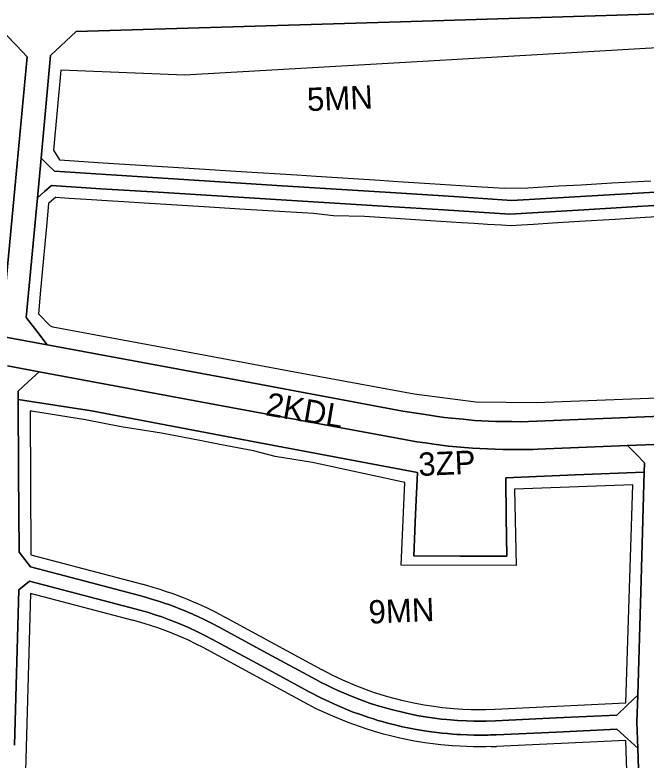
# Model space of a CAD drawing. Extents: x 7418021 to 7419743, y 5540231 to 5541685.
# Drawn here: x 7419069.1 to 7419339.9, y 5540706.1 to 5541025.9 of the extents above; entities that cross this region are included whole.
import ezdxf

# ---------------------------------------------------------------- set-up
doc = ezdxf.new("R2010")
doc.units = 0
for name, color, linetype in [('linie_rozgraniczajace', 7, 'Continuous'), ('linie_zabudowy_nieprzekraczalne', 7, 'Continuous'), ('linie_zabudowy_obowiazujace', 7, 'Continuous'), ('oznaczenia_przeznaczen', 7, 'Continuous')]:
    doc.layers.add(name, color=color, linetype=linetype)

msp = doc.modelspace()

# ---------------------------------------------------------------- linework, layer by layer
at = {"layer": 'linie_rozgraniczajace'}
for points in [[(7419373.79, 5541027.27), (7419234.54, 5541023), (7419095.29, 5541018.74), (7419084.37, 5541008.48), (7419080.29, 5540964.41), (7419078.72, 5540947.43), (7419073.96, 5540896.09), (7419078.43, 5540890.2), (7419082.87, 5540884.31), (7419053.34, 5540889.78), (7419058.73, 5540893.85), (7419064.09, 5540897.92), (7419069.18, 5540952.92), (7419074.28, 5541007.93), (7419069.74, 5541012.72), (7419065.21, 5541017.52), (7419045.63, 5541016.89), (7419026.05, 5541016.25), (7419014.29, 5541017.62), (7419002.54, 5541018.98), (7418996.01, 5541020.4), (7418989.47, 5541021.83), (7418984.55, 5541023.35), (7418974.12, 5541026.58)], [(7419065.21, 5541017.52), (7419069.74, 5541012.72), (7419074.28, 5541007.93), (7419069.18, 5540952.92), (7419064.09, 5540897.92)], [(7419363.96, 5540945.38), (7419313.1, 5540942.32), (7419281.37, 5540940.41), (7419252.97, 5540942.22), (7419224.57, 5540944.04), (7419130.54, 5540949.78), (7419105.96, 5540951.31), (7419084.74, 5540952.69), (7419081.73, 5540950.06), (7419078.72, 5540947.43), (7419080.29, 5540964.41), (7419083.17, 5540961.6), (7419086.04, 5540958.8), (7419134.88, 5540955.7), (7419183.71, 5540952.61), (7419232.55, 5540949.52), (7419257.39, 5540947.92), (7419282.22, 5540946.32), (7419385.59, 5540952.23)], [(7419470.75, 5540858.74), (7419292.97, 5540851.53), (7419285.88, 5540851.34), (7419282.27, 5540851.35), (7419278.66, 5540851.37), (7419275.44, 5540851.47), (7419272.23, 5540851.57), (7419269.25, 5540851.74), (7419266.27, 5540851.91), (7419261.35, 5540852.36), (7419256.44, 5540852.8), (7419253.43, 5540853.17), (7419250.42, 5540853.54), (7419246.95, 5540854.07), (7419241.21, 5540854.99), (7419235.47, 5540855.91), (7419160.91, 5540869.85), (7419082.87, 5540884.31), (7419078.43, 5540890.2), (7419073.96, 5540896.09), (7419078.72, 5540947.43), (7419081.73, 5540950.06), (7419084.74, 5540952.69), (7419105.96, 5540951.31), (7419130.54, 5540949.78), (7419224.57, 5540944.04), (7419252.97, 5540942.22), (7419281.37, 5540940.41), (7419313.1, 5540942.32), (7419363.96, 5540945.38)], [(7419053.34, 5540889.78), (7419082.87, 5540884.31), (7419160.91, 5540869.85), (7419235.47, 5540855.91), (7419241.21, 5540854.99), (7419246.95, 5540854.07), (7419250.42, 5540853.54), (7419253.43, 5540853.17), (7419256.44, 5540852.8), (7419261.35, 5540852.36), (7419266.27, 5540851.91), (7419269.25, 5540851.74), (7419272.23, 5540851.57), (7419275.44, 5540851.47), (7419278.66, 5540851.37), (7419282.27, 5540851.35), (7419285.88, 5540851.34), (7419292.97, 5540851.53), (7419470.75, 5540858.74)], [(7419355.09, 5540842.04), (7419331.92, 5540841.1), (7419293.45, 5540839.54), (7419291.47, 5540839.47), (7419289.57, 5540839.41), (7419287.68, 5540839.37), (7419285.97, 5540839.34), (7419282.21, 5540839.36), (7419278.45, 5540839.37), (7419275.07, 5540839.48), (7419268.54, 5540839.76), (7419265.39, 5540839.94), (7419260.27, 5540840.41), (7419255.16, 5540840.87), (7419251.98, 5540841.26), (7419248.79, 5540841.65), (7419245.17, 5540842.2), (7419241.54, 5540842.75), (7419236.87, 5540843.57), (7419158.72, 5540858.05), (7419079.41, 5540872.75), (7419065.92, 5540875.25)], [(7419065.92, 5540875.25), (7419079.41, 5540872.75), (7419074.91, 5540868.61), (7419070.4, 5540864.47), (7419070.43, 5540860.86), (7419070.67, 5540829.88), (7419070.94, 5540795.28), (7419073.38, 5540792.15), (7419075.81, 5540789.01), (7419099.2, 5540782.86), (7419122.58, 5540776.71), (7419124.13, 5540776.29), (7419125.48, 5540775.9), (7419126.83, 5540775.52), (7419128.28, 5540775.08), (7419131.08, 5540774.2), (7419132.43, 5540773.76), (7419133.56, 5540773.37), (7419134.68, 5540772.98), (7419136.93, 5540772.17), (7419138.18, 5540771.69), (7419139.44, 5540771.21), (7419140.47, 5540770.79), (7419142.4, 5540770.01), (7419144.23, 5540769.23), (7419145.17, 5540768.83), (7419146.18, 5540768.37), (7419147.2, 5540767.92), (7419148.17, 5540767.47), (7419149.94, 5540766.63), (7419151.73, 5540765.75), (7419153.73, 5540764.74), (7419156.66, 5540763.2), (7419177.42, 5540751.92), (7419198.19, 5540740.64), (7419200.51, 5540739.43), (7419202.84, 5540738.23), (7419205.21, 5540737.1), (7419207.59, 5540735.97), (7419210.3, 5540734.8), (7419213.02, 5540733.63), (7419217.1, 5540732.11), (7419221.18, 5540730.6), (7419224.34, 5540729.6), (7419227.5, 5540728.61), (7419230.6, 5540727.79), (7419236.48, 5540726.35), (7419241.53, 5540725.31), (7419245.94, 5540724.56), (7419248.08, 5540724.23), (7419250.04, 5540723.98), (7419251.99, 5540723.74), (7419254.45, 5540723.5), (7419258.95, 5540723.14), (7419262.85, 5540722.94), (7419266.01, 5540722.85), (7419271.2, 5540722.85), (7419275.25, 5540722.99), (7419301.31, 5540724.21), (7419327.38, 5540725.44), (7419331.82, 5540729.73), (7419336.27, 5540734.01), (7419335.88, 5540722.36), (7419336.33, 5540711.28), (7419331.84, 5540715.3), (7419327.34, 5540719.32), (7419301.44, 5540718.16), (7419275.53, 5540716.99), (7419274.33, 5540716.95), (7419273.13, 5540716.9), (7419272.07, 5540716.87), (7419271, 5540716.85), (7419268.45, 5540716.85), (7419265.91, 5540716.84), (7419263.1, 5540716.94), (7419260.29, 5540717.04), (7419258.64, 5540717.14), (7419256.99, 5540717.25), (7419254.65, 5540717.46), (7419252.31, 5540717.67), (7419249, 5540718.09), (7419245.7, 5540718.51), (7419241.43, 5540719.21), (7419238.36, 5540719.82), (7419235.3, 5540720.44), (7419233.66, 5540720.82), (7419232.03, 5540721.19), (7419230.26, 5540721.65), (7419228.49, 5540722.1), (7419226.63, 5540722.63), (7419224.76, 5540723.16), (7419222.87, 5540723.75), (7419220.98, 5540724.34), (7419217.38, 5540725.61), (7419213.78, 5540726.89), (7419207.4, 5540729.48), (7419200.58, 5540732.65), (7419195.33, 5540735.37), (7419174.56, 5540746.65)], [(7419331.92, 5540841.1), (7419355.09, 5540842.04)], [(7419337.76, 5540666.96), (7419336.33, 5540711.28), (7419335.88, 5540722.36), (7419336.27, 5540734.01), (7419337.57, 5540778.37), (7419339.07, 5540829.66), (7419339.19, 5540833.66), (7419335.55, 5540837.38), (7419331.92, 5540841.1)], [(7419174.56, 5540746.65), (7419153.8, 5540757.92), (7419150.61, 5540759.6), (7419147.34, 5540761.21), (7419143.54, 5540762.98), (7419141.77, 5540763.76), (7419139.85, 5540764.56), (7419137.94, 5540765.35), (7419135, 5540766.44), (7419132.07, 5540767.54), (7419129.22, 5540768.47), (7419126.36, 5540769.4), (7419121.05, 5540770.9), (7419098.18, 5540776.92), (7419075.31, 5540782.94), (7419073.03, 5540781.08), (7419070.75, 5540779.22), (7419068.86, 5540712.48)], [(7419068.86, 5540712.48), (7419070.75, 5540779.22), (7419073.03, 5540781.08), (7419075.31, 5540782.94), (7419098.18, 5540776.92), (7419121.05, 5540770.9), (7419126.36, 5540769.4), (7419129.22, 5540768.47), (7419132.07, 5540767.54), (7419135, 5540766.44), (7419137.94, 5540765.35), (7419139.85, 5540764.56), (7419141.77, 5540763.76), (7419143.54, 5540762.98), (7419147.34, 5540761.21), (7419150.61, 5540759.6), (7419153.8, 5540757.92), (7419174.56, 5540746.65), (7419195.33, 5540735.37), (7419200.58, 5540732.65), (7419207.4, 5540729.48), (7419213.78, 5540726.89), (7419217.38, 5540725.61), (7419220.98, 5540724.34), (7419222.87, 5540723.75), (7419224.76, 5540723.16), (7419226.63, 5540722.63), (7419228.49, 5540722.1), (7419230.26, 5540721.65), (7419232.03, 5540721.19), (7419233.66, 5540720.82), (7419235.3, 5540720.44), (7419238.36, 5540719.82), (7419241.43, 5540719.21), (7419245.7, 5540718.51), (7419249, 5540718.09), (7419252.31, 5540717.67), (7419254.65, 5540717.46), (7419256.99, 5540717.25), (7419258.64, 5540717.14), (7419260.29, 5540717.04), (7419263.1, 5540716.94), (7419265.91, 5540716.84), (7419268.45, 5540716.85), (7419271, 5540716.85), (7419272.07, 5540716.87), (7419273.13, 5540716.9), (7419274.33, 5540716.95), (7419275.53, 5540716.99), (7419301.44, 5540718.16), (7419327.34, 5540719.32), (7419331.84, 5540715.3), (7419336.33, 5540711.28), (7419337.76, 5540666.96)]]:
    msp.add_lwpolyline(points, dxfattribs=at)
for points in [[(7419095.29, 5541018.74), (7419234.54, 5541023), (7419373.79, 5541027.27), (7419464.79, 5541028.03), (7419557.71, 5541028.81), (7419559.74, 5541026.38), (7419561.78, 5541023.94), (7419553.94, 5540993.88), (7419546.61, 5540965.74), (7419543.38, 5540963.37), (7419540.14, 5540961), (7419488.96, 5540958.13), (7419385.59, 5540952.23), (7419282.22, 5540946.32), (7419257.39, 5540947.92), (7419232.55, 5540949.52), (7419183.71, 5540952.61), (7419134.88, 5540955.7), (7419086.04, 5540958.8), (7419083.17, 5540961.6), (7419080.29, 5540964.41), (7419084.37, 5541008.48)], [(7419079.41, 5540872.75), (7419158.72, 5540858.05), (7419236.87, 5540843.57), (7419241.54, 5540842.75), (7419245.17, 5540842.2), (7419248.79, 5540841.65), (7419251.98, 5540841.26), (7419255.16, 5540840.87), (7419260.27, 5540840.41), (7419265.39, 5540839.94), (7419268.54, 5540839.76), (7419275.07, 5540839.48), (7419278.45, 5540839.37), (7419282.21, 5540839.36), (7419285.97, 5540839.34), (7419287.68, 5540839.37), (7419289.57, 5540839.41), (7419291.47, 5540839.47), (7419293.45, 5540839.54), (7419331.92, 5540841.1), (7419335.55, 5540837.38), (7419339.19, 5540833.66), (7419339.07, 5540829.66), (7419309.4, 5540828.46), (7419279.74, 5540827.25), (7419279.9, 5540810.41), (7419280.06, 5540793.57), (7419260.12, 5540793.66), (7419240.17, 5540793.74), (7419241, 5540811.6), (7419241.82, 5540829.46), (7419171.88, 5540842.73), (7419101.94, 5540856.01), (7419086.18, 5540858.43), (7419070.43, 5540860.86), (7419070.4, 5540864.47), (7419074.91, 5540868.61)], [(7419070.43, 5540860.86), (7419086.18, 5540858.43), (7419101.94, 5540856.01), (7419171.88, 5540842.73), (7419241.82, 5540829.46), (7419241, 5540811.6), (7419240.17, 5540793.74), (7419260.12, 5540793.66), (7419280.06, 5540793.57), (7419279.9, 5540810.41), (7419279.74, 5540827.25), (7419309.4, 5540828.46), (7419339.07, 5540829.66), (7419337.57, 5540778.37), (7419336.27, 5540734.01), (7419331.82, 5540729.73), (7419327.38, 5540725.44), (7419301.31, 5540724.21), (7419275.25, 5540722.99), (7419271.2, 5540722.85), (7419266.01, 5540722.85), (7419262.85, 5540722.94), (7419258.95, 5540723.14), (7419254.45, 5540723.5), (7419251.99, 5540723.74), (7419250.04, 5540723.98), (7419248.08, 5540724.23), (7419245.94, 5540724.56), (7419241.53, 5540725.31), (7419236.48, 5540726.35), (7419230.6, 5540727.79), (7419227.5, 5540728.61), (7419224.34, 5540729.6), (7419221.18, 5540730.6), (7419217.1, 5540732.11), (7419213.02, 5540733.63), (7419210.3, 5540734.8), (7419207.59, 5540735.97), (7419205.21, 5540737.1), (7419202.84, 5540738.23), (7419200.51, 5540739.43), (7419198.19, 5540740.64), (7419177.42, 5540751.92), (7419156.66, 5540763.2), (7419153.73, 5540764.74), (7419151.73, 5540765.75), (7419149.94, 5540766.63), (7419148.17, 5540767.47), (7419147.2, 5540767.92), (7419146.18, 5540768.37), (7419145.17, 5540768.83), (7419144.23, 5540769.23), (7419142.4, 5540770.01), (7419140.47, 5540770.79), (7419139.44, 5540771.21), (7419138.18, 5540771.69), (7419136.93, 5540772.17), (7419134.68, 5540772.98), (7419133.56, 5540773.37), (7419132.43, 5540773.76), (7419131.08, 5540774.2), (7419128.28, 5540775.08), (7419126.83, 5540775.52), (7419125.48, 5540775.9), (7419124.13, 5540776.29), (7419122.58, 5540776.71), (7419099.2, 5540782.86), (7419075.81, 5540789.01), (7419073.38, 5540792.15), (7419070.94, 5540795.28), (7419070.67, 5540829.88)]]:
    msp.add_lwpolyline(points, close=True, dxfattribs=at)
at = {"layer": 'linie_zabudowy_nieprzekraczalne'}
for points in [[(7419383.77, 5541014.03), (7419244.03, 5541005.91)], [(7419244.03, 5541005.91), (7419142.02, 5540999.99)], [(7419088.81, 5541002.19), (7419085.63, 5540967.79)], [(7419142.02, 5540999.99), (7419088.81, 5541002.19)], [(7419085.63, 5540967.79), (7419088.2, 5540963.67)], [(7419088.2, 5540963.67), (7419106.97, 5540962.48)], [(7419106.97, 5540962.48), (7419141.6, 5540960.29)], [(7419141.6, 5540960.29), (7419166.21, 5540958.73)], [(7419166.21, 5540958.73), (7419189.96, 5540957.23)], [(7419189.96, 5540957.23), (7419198.32, 5540956.7)], [(7419198.32, 5540956.7), (7419225.69, 5540954.96)], [(7419225.69, 5540954.96), (7419233.35, 5540954.48)], [(7419233.35, 5540954.48), (7419247.13, 5540953.59)], [(7419247.13, 5540953.59), (7419264.82, 5540952.45)], [(7419264.82, 5540952.45), (7419279.05, 5540951.54)], [(7419289.19, 5540951.73), (7419302.45, 5540952.49)], [(7419302.45, 5540952.49), (7419312, 5540953.03)], [(7419312, 5540953.03), (7419325.1, 5540953.78)], [(7419325.1, 5540953.78), (7419341.84, 5540954.74)], [(7419279.05, 5540951.54), (7419289.19, 5540951.73)], [(7419086.57, 5540947.65), (7419083.51, 5540944.98)], [(7419086.48, 5540947.57), (7419083.51, 5540944.98)], [(7419092.37, 5540947.19), (7419086.48, 5540947.57)], [(7419099.58, 5540946.72), (7419092.37, 5540947.19)], [(7419110.89, 5540946), (7419099.58, 5540946.72)], [(7419083.51, 5540944.98), (7419082.6, 5540935.07)], [(7419115.87, 5540945.69), (7419110.89, 5540946)], [(7419124.48, 5540945.15), (7419115.87, 5540945.69)], [(7419138.53, 5540944.27), (7419124.48, 5540945.15)], [(7419154.64, 5540943.27), (7419138.53, 5540944.27)], [(7419165.5, 5540942.61), (7419154.64, 5540943.27)], [(7419411.21, 5540943.03), (7419339.5, 5540938.9)], [(7419197.15, 5540940.69), (7419165.5, 5540942.61)], [(7419205.76, 5540939.69), (7419197.15, 5540940.69)], [(7419219.03, 5540939.37), (7419205.76, 5540939.69)], [(7419234.47, 5540938.4), (7419219.03, 5540939.37)], [(7419247.41, 5540937.57), (7419234.47, 5540938.4)], [(7419260.66, 5540936.73), (7419247.41, 5540937.57)], [(7419266.1, 5540936.38), (7419260.66, 5540936.73)], [(7419299.77, 5540936.51), (7419291.62, 5540936.02)], [(7419311.27, 5540937.2), (7419299.77, 5540936.51)], [(7419326.57, 5540938.13), (7419311.27, 5540937.2)], [(7419339.5, 5540938.9), (7419326.57, 5540938.13)], [(7419082.6, 5540935.07), (7419081.62, 5540924.54)], [(7419271.79, 5540936.02), (7419266.1, 5540936.38)], [(7419277.82, 5540935.63), (7419271.79, 5540936.02)], [(7419281.94, 5540935.44), (7419277.82, 5540935.63)], [(7419286.47, 5540935.71), (7419281.94, 5540935.44)], [(7419291.62, 5540936.02), (7419286.47, 5540935.71)], [(7419081.62, 5540924.54), (7419080.06, 5540907.71)], [(7419080.06, 5540907.71), (7419079.12, 5540897.56)], [(7419079.12, 5540897.56), (7419084.14, 5540892.42)], [(7419084.14, 5540892.42), (7419085.28, 5540892)], [(7419075.56, 5540855.91), (7419075.95, 5540794.15)], [(7419331.18, 5540730.63), (7419334.19, 5540824.27)], [(7419075.95, 5540794.15), (7419123.86, 5540781.54)], [(7419123.88, 5540781.54), (7419125.46, 5540781.11)], [(7419125.46, 5540781.11), (7419128.25, 5540780.32)], [(7419128.25, 5540780.32), (7419131.24, 5540779.41)], [(7419075.71, 5540777.67), (7419071.98, 5540645.61)], [(7419119.78, 5540766.07), (7419075.71, 5540777.67)], [(7419131.24, 5540779.41), (7419134.03, 5540778.5)], [(7419134.03, 5540778.5), (7419136.36, 5540777.69)], [(7419136.36, 5540777.69), (7419138.67, 5540776.85)], [(7419138.67, 5540776.85), (7419141.26, 5540775.87)], [(7419141.26, 5540775.87), (7419143.4, 5540775.01)], [(7419143.4, 5540775.01), (7419145.24, 5540774.24)], [(7419145.24, 5540774.24), (7419147.18, 5540773.41)], [(7419147.18, 5540773.41), (7419149.28, 5540772.47)], [(7419149.28, 5540772.47), (7419151.28, 5540771.54)], [(7419151.28, 5540771.54), (7419152.95, 5540770.74)], [(7419152.95, 5540770.74), (7419154.97, 5540769.73)], [(7419154.97, 5540769.73), (7419157.07, 5540768.65)], [(7419157.07, 5540768.65), (7419158.17, 5540768.06)], [(7419158.17, 5540768.06), (7419159.19, 5540767.51)], [(7419159.05, 5540767.59), (7419200.58, 5540745.04)], [(7419124.91, 5540764.62), (7419119.69, 5540766.1)], [(7419130.42, 5540762.82), (7419124.91, 5540764.62)], [(7419136.11, 5540760.7), (7419130.42, 5540762.82)], [(7419139.8, 5540759.17), (7419136.11, 5540760.7)], [(7419143.2, 5540757.65), (7419139.8, 5540759.17)], [(7419147.15, 5540755.76), (7419143.2, 5540757.65)], [(7419149.54, 5540754.53), (7419147.15, 5540755.76)], [(7419151.45, 5540753.52), (7419149.54, 5540754.53)], [(7419192.99, 5540730.96), (7419151.41, 5540753.53)], [(7419200.5, 5540745.08), (7419205.07, 5540742.7)], [(7419205.07, 5540742.7), (7419209.65, 5540740.52)], [(7419209.65, 5540740.52), (7419214.88, 5540738.28)], [(7419214.88, 5540738.28), (7419222.8, 5540735.33)], [(7419222.8, 5540735.33), (7419228.89, 5540733.42)], [(7419228.89, 5540733.42), (7419234.88, 5540731.83)], [(7419234.88, 5540731.83), (7419240.27, 5540730.63)], [(7419198.38, 5540728.16), (7419192.99, 5540730.96)], [(7419240.27, 5540730.63), (7419244.63, 5540729.82)], [(7419244.63, 5540729.82), (7419248.78, 5540729.18)], [(7419248.78, 5540729.18), (7419252.54, 5540728.71)], [(7419252.54, 5540728.71), (7419257.31, 5540728.26)], [(7419275.02, 5540727.98), (7419331.18, 5540730.63)], [(7419205.41, 5540724.9), (7419198.38, 5540728.16)], [(7419257.31, 5540728.26), (7419261.25, 5540728)], [(7419261.25, 5540728), (7419264.85, 5540727.87)], [(7419264.85, 5540727.87), (7419267.33, 5540727.83)], [(7419267.33, 5540727.83), (7419271.1, 5540727.85)], [(7419271.1, 5540727.85), (7419275.09, 5540727.99)], [(7419212, 5540722.21), (7419205.41, 5540724.9)], [(7419219.41, 5540719.6), (7419212, 5540722.21)], [(7419223.34, 5540718.37), (7419219.41, 5540719.6)], [(7419227.19, 5540717.28), (7419223.34, 5540718.37)], [(7419230.85, 5540716.34), (7419227.19, 5540717.28)], [(7419234.24, 5540715.55), (7419230.85, 5540716.34)], [(7419240.54, 5540714.29), (7419234.24, 5540715.55)], [(7419244.98, 5540713.56), (7419240.54, 5540714.29)], [(7419251.77, 5540712.7), (7419244.98, 5540713.56)], [(7419256.61, 5540712.26), (7419251.77, 5540712.7)], [(7419331.23, 5540714.49), (7419275.76, 5540712)], [(7419334.58, 5540610.85), (7419331.23, 5540714.49)], [(7419260.05, 5540712.04), (7419256.61, 5540712.26)], [(7419265.82, 5540711.85), (7419260.05, 5540712.04)], [(7419271.07, 5540711.85), (7419265.82, 5540711.85)], [(7419273.26, 5540711.9), (7419271.07, 5540711.85)], [(7419273.33, 5540711.91), (7419275.73, 5540712)]]:
    msp.add_lwpolyline(points, dxfattribs=at)
at = {"layer": 'linie_zabudowy_obowiazujace'}
for points in [[(7419085.27, 5540892), (7419113.86, 5540886.71), (7419140.77, 5540881.72), (7419186.8, 5540873.19)], [(7419186.8, 5540873.19), (7419240.33, 5540863.27), (7419266.86, 5540859.9), (7419292.65, 5540859.52), (7419344.76, 5540861.64)], [(7419196.68, 5540833.82), (7419180.68, 5540836.45), (7419171.4, 5540838.76), (7419157.69, 5540841.4), (7419148.44, 5540843.27), (7419131.94, 5540846.34), (7419114.68, 5540849.09), (7419099.29, 5540852.15), (7419076.18, 5540855.83), (7419075.56, 5540855.91)], [(7419234.74, 5540789.8), (7419236.43, 5540825.18), (7419196.68, 5540833.82)], [(7419334.19, 5540824.27), (7419283.43, 5540822.32), (7419284.11, 5540789.55), (7419234.74, 5540789.8)]]:
    msp.add_lwpolyline(points, dxfattribs=at)

# ---------------------------------------------------------------- texts
at = {"layer": 'oznaczenia_przeznaczen'}
for s, rotation, p in [('5MN', 2.396, (7419194.58, 5540984.59)), ('2KDL', 350.292, (7419176.21, 5540854.14)), ('3ZP', 2.5711, (7419242.37, 5540828)), ('9MN', 2.396, (7419220.99, 5540764.63))]:
    msp.add_text(s, height=10, rotation=rotation, dxfattribs=at).set_placement(p)

doc.saveas('drawing.dxf')
